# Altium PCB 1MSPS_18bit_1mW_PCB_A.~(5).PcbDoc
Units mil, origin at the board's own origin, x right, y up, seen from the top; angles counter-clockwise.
Board outline 3200 x 1700 mil, 4 copper layers (Top, Inner Layer 2, Inner Layer 3, Bottom), stack 35.4 mil thick; 66 components, 41 nets, 208 pads, 43 vias.
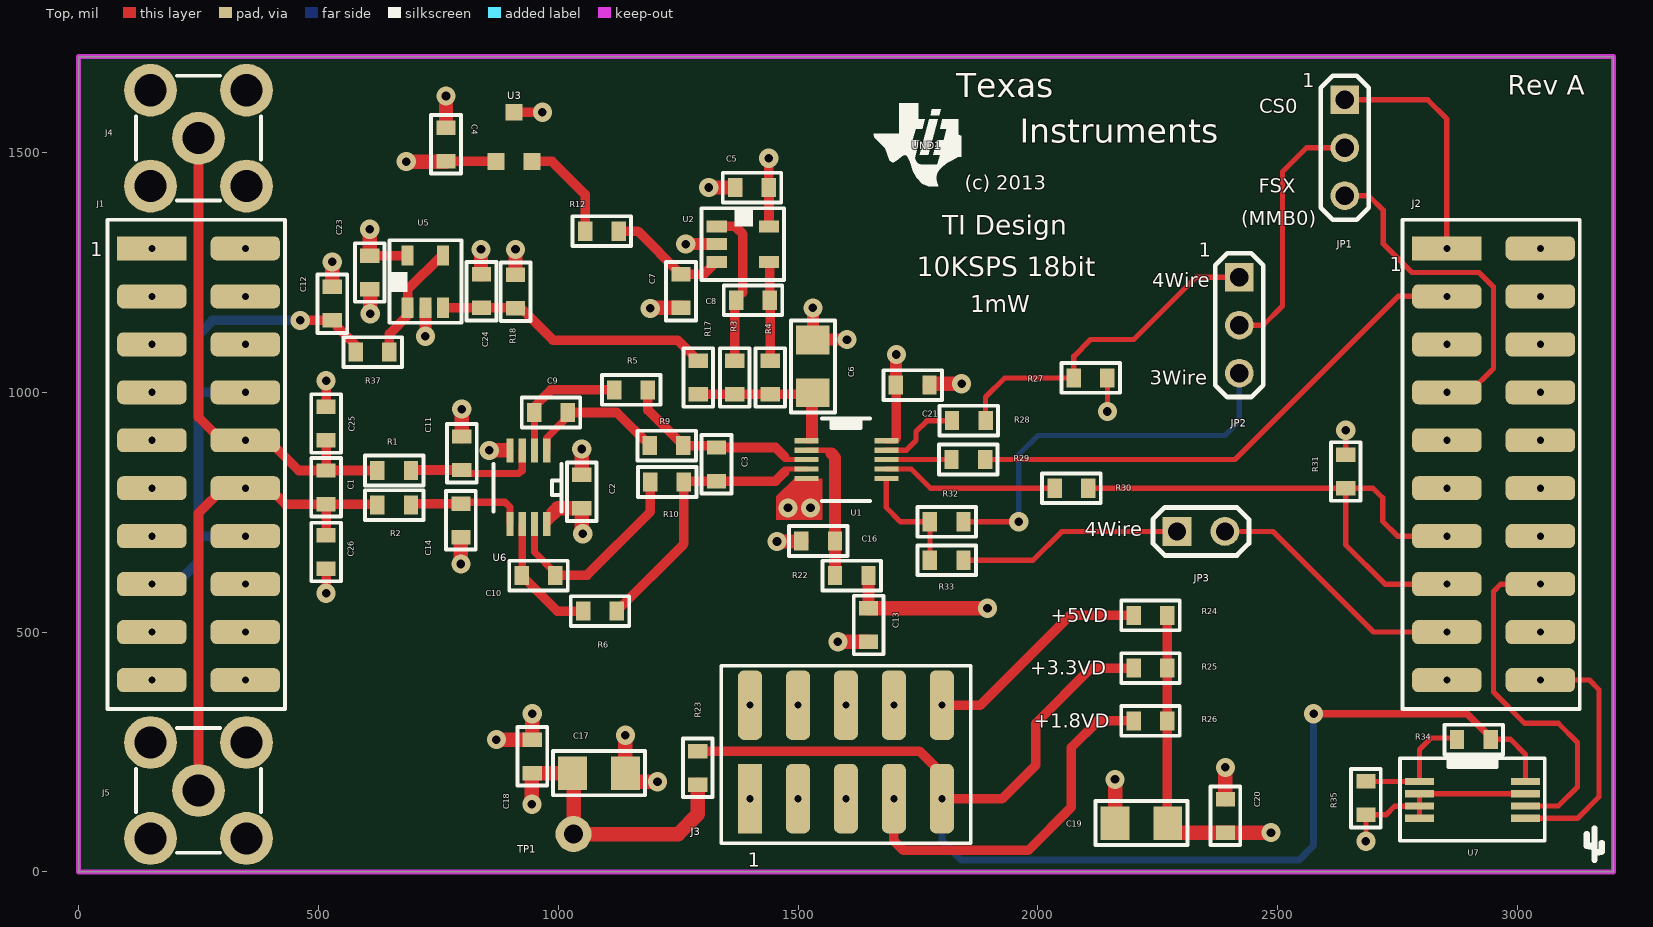
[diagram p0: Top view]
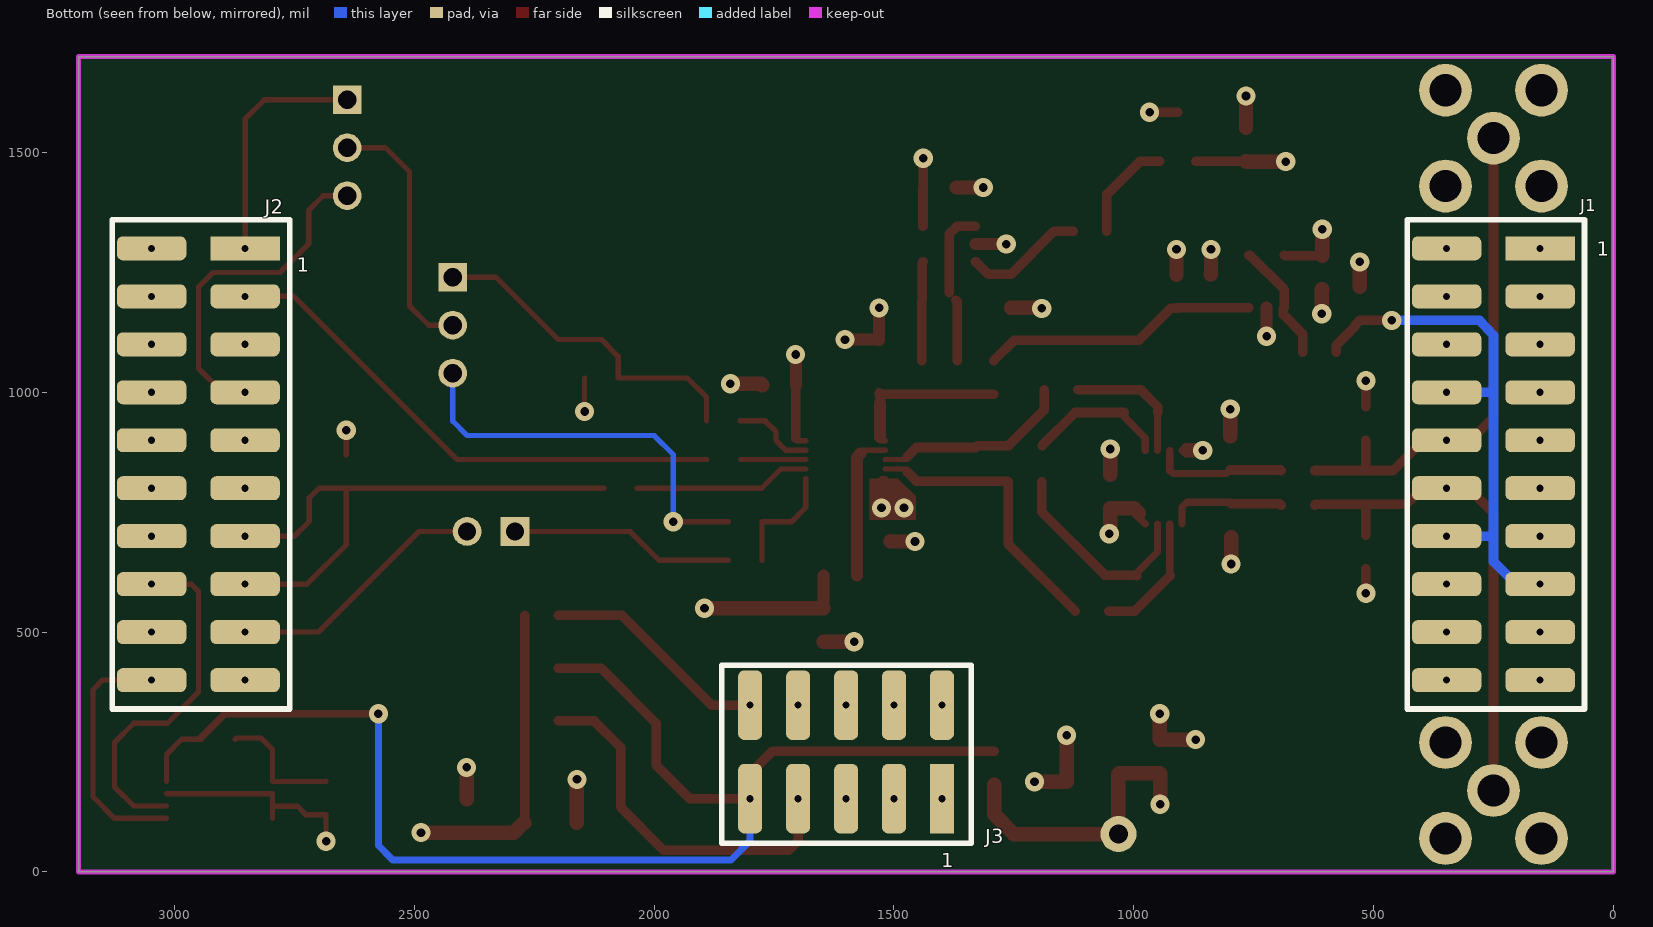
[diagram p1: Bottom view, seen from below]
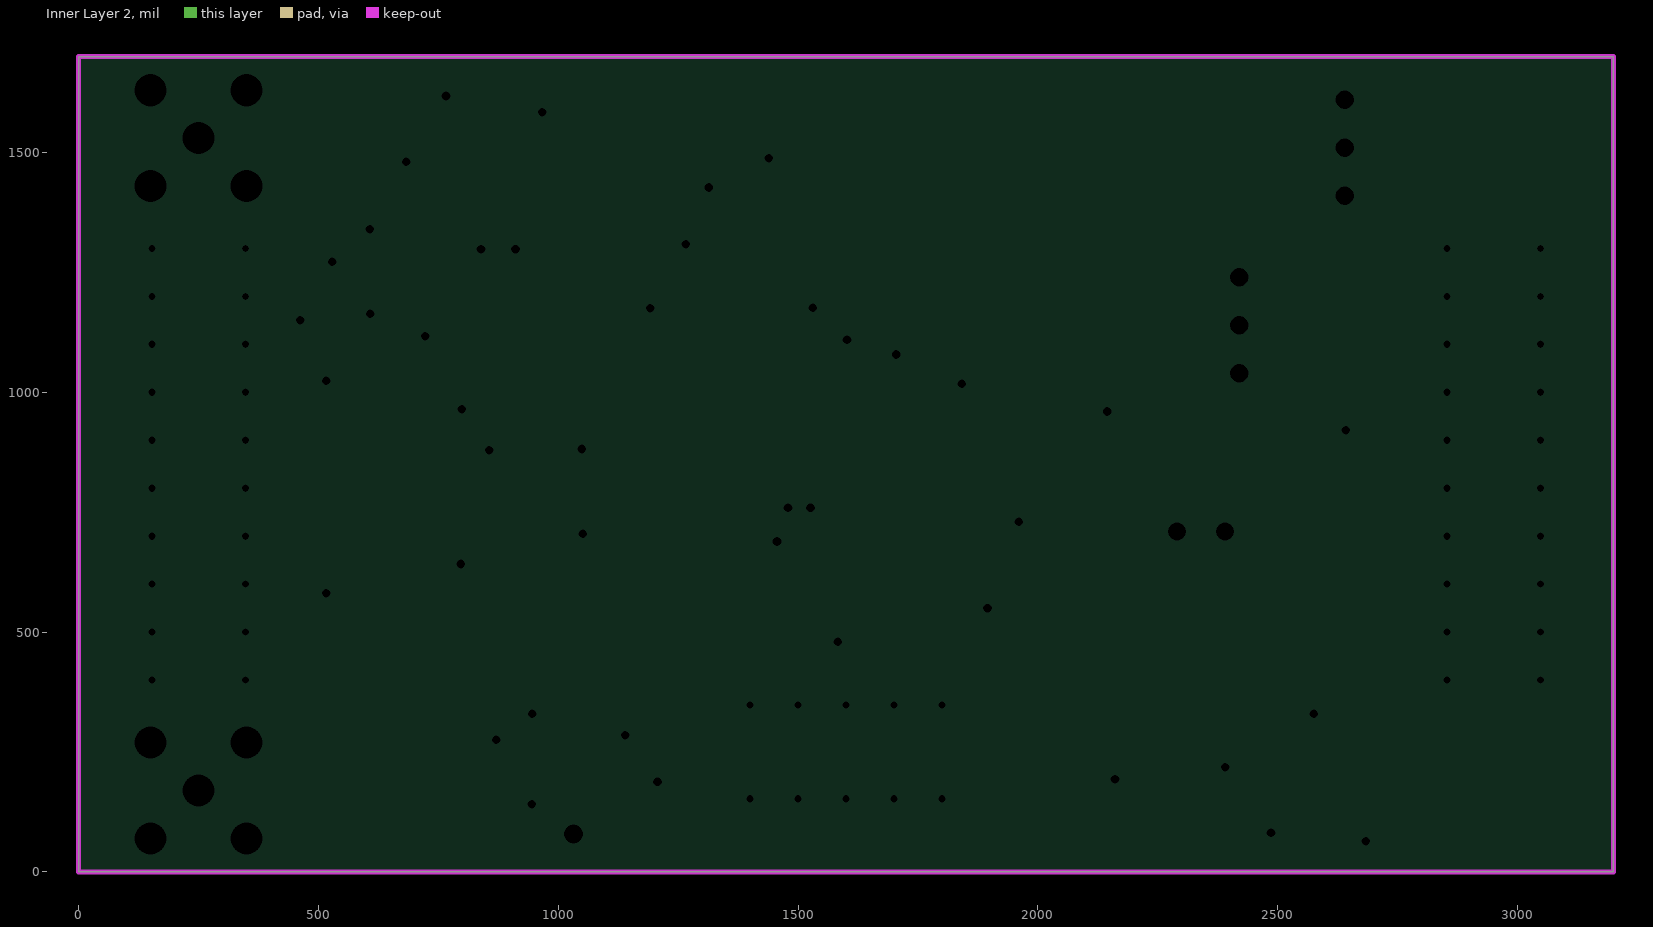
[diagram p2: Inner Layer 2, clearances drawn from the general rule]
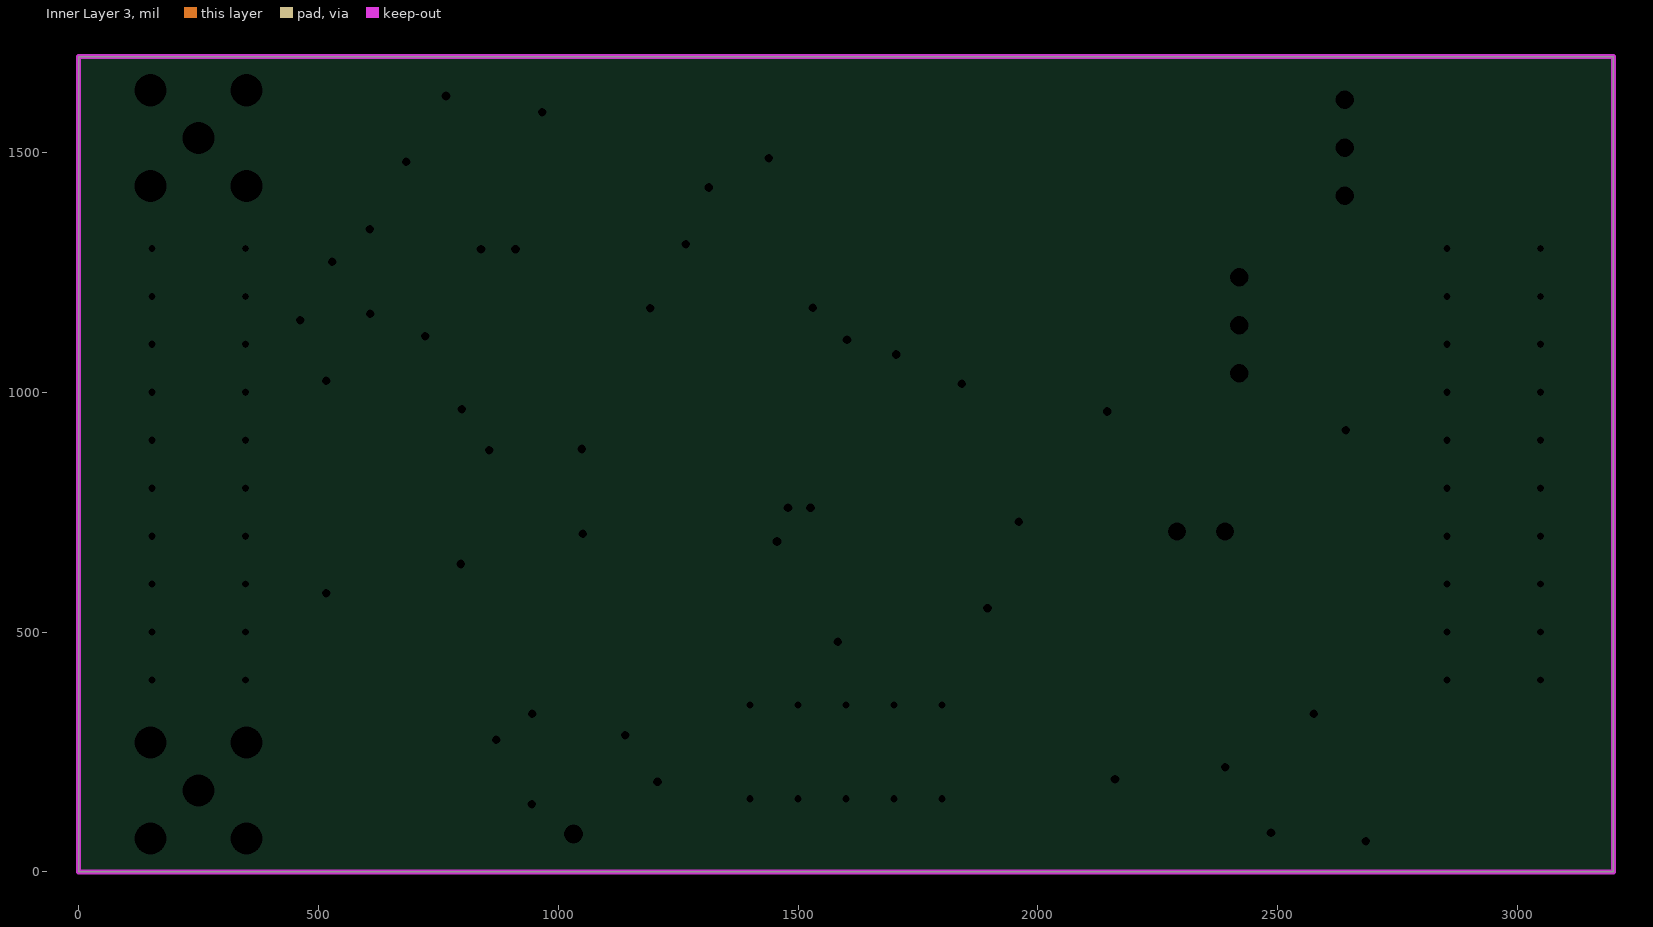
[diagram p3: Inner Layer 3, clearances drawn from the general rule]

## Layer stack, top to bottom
Top: signal copper 1.35
Dielectric: dielectric 10, FR-4, Dk 4.3
Inner Layer 2: plane copper 1.35
Dielectric: dielectric 10, FR-4, Dk 4.3
Inner Layer 3: plane copper 1.35
Dielectric: dielectric 10, FR-4, Dk 4.3
Bottom: signal copper 1.35

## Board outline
0,0 3200,0 3200,1700 0,1700

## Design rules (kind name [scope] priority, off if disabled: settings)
Clearance "'Default' PADS rule_18" [All] p1: gap=7
Clearance "'Default' PADS rule_15" [IsVia vs IsVia] p2: gap=7
ComponentClearance "'Default' PADS rule_12" [All] p1: gap=7 collisioncheckmode=3 verticalgap=10 showdistances=FALSE
FlightTimeFalling "'Default' PADS rule_10" [All] p1: maximum=10.00
FlightTimeRising "'Default' PADS rule_9" [All] p1: maximum=10.00
Length "'Default' PADS rule_5" [All] p1: maxlimit=50000 minlimit=0
MatchedLengths "'Default' PADS rule_11" [InNetClass('All Nets')] p1: tolerance=200 checknetsindiffpair=TRUE checkdiffpairvsdiffpair=TRUE checkothers=TRUE
MaxMinImpedance "'Default' PADS rule_8" [All] p1: minimum=50.00 maximum=150.0
ParallelSegment "'Default' PADS rule_7" [All] p1: limit=1000 gap=200
ParallelSegment "'Default' PADS rule_6" [All] p2: limit=1000 gap=200
PlaneClearance "'Default' PADS rule_14" [All] p1: clearance=7
PlaneConnect "Power Plane Connect Style for STDPCADVIA" [IsVia And (ViaDiameter=40) And (HoleSize=18)] p1: planeconnectstyle=Relief reliefexpansion=11 reliefentries=4 reliefconductorwidth=10 reliefairgap=10
PlaneConnect "Power Plane Connect Style for J3-5" [(Name='J3-5')] p2: planeconnectstyle=Relief reliefexpansion=7.5 reliefentries=4 reliefconductorwidth=20 reliefairgap=5
PlaneConnect "Power Plane Connect Style - pads with no thermal" [(Name='J2-2') Or (Name='J2-5') Or (Name='J2-6') Or (Name='J2-8') Or (Name='J2-9') Or (Name='J2-11') Or (Name='J2-12') Or (Name='J2-14') Or (Name='J2-19') Or (Name='J3-1') Or (Name='J3-2') Or (Name='J3-3') Or (Name='J3-4') Or (Name='J3-8') Or (Name='TP1-1')] p3: planeconnectstyle=NoConnect reliefexpansion=20 reliefentries=4 reliefconductorwidth=10 reliefairgap=10 // PAD - No Thermal Connect Rule
PlaneConnect "Power Plane Connect Style for J1-1" [(Name='J1-1')] p4: planeconnectstyle=Relief reliefexpansion=17.5 reliefentries=4 reliefconductorwidth=10 reliefairgap=10
PlaneConnect "Power Plane Connect Style - Via from round thru-hole global defaults" [IsVia] p5: planeconnectstyle=Relief reliefexpansion=20 reliefentries=4 reliefconductorwidth=10 reliefairgap=10
PlaneConnect "Power Plane Connect Style - Round thru-hole pad from global defaults" [IsPad And OnMultiLayer And (PadShape_MidLayer1 = 'Round') And (PadXSize_MidLayer1 = PadYSize_MidLayer1)] p6: planeconnectstyle=Relief reliefexpansion=20 reliefentries=4 reliefconductorwidth=10 reliefairgap=10
PlaneConnect "Power Plane Connect Style - Square thru-hole pad from global defaults" [IsPad And OnMultiLayer And ((PadShape_MidLayer1 = 'Rectangular') Or (PadShape_MidLayer1 = 'Octagonal') Or (PadShape_MidLayer1 = 'Rounded Rectangle')) And (PadXSize_MidLayer1 = PadYSize_MidLayer1)] p7: planeconnectstyle=Direct reliefexpansion=20 reliefentries=4 reliefconductorwidth=10 reliefairgap=10
PlaneConnect "Power Plane Connect Style - Rect thru-hole pad from global defaults" [IsPad And OnMultiLayer And ((PadShape_MidLayer1 = 'Rectangular') Or (PadShape_MidLayer1 = 'Octagonal') Or (PadShape_MidLayer1 = 'Rounded Rectangle')) And (PadXSize_MidLayer1 <> PadYSize_MidLayer1)] p8: planeconnectstyle=Direct reliefexpansion=20 reliefentries=4 reliefconductorwidth=10 reliefairgap=10
PlaneConnect "Power Plane Connect Style - Square-rect thru-hole pad from global defaults" [IsPad And OnMultiLayer And (PadShape_MidLayer1 = 'Rounded Rectangle') And (PadXSize_MidLayer1 = PadYSize_MidLayer1) And (Pad_CornerRadius_MidLayer1 = '0%')] p9: planeconnectstyle=Direct reliefexpansion=20 reliefentries=4 reliefconductorwidth=10 reliefairgap=10
PlaneConnect "Power Plane Connect Style - Oval thru-hole pad from global defaults" [IsPad And OnMultiLayer And (PadShape_MidLayer1 = 'Round') And (PadXSize_MidLayer1 <> PadYSize_MidLayer1)] p10: planeconnectstyle=Direct reliefexpansion=20 reliefentries=4 reliefconductorwidth=10 reliefairgap=10
PlaneConnect "Power Plane Connect Style - Round-oval thru-hole pad from global defaults" [IsPad And OnMultiLayer And (PadShape_MidLayer1 = 'Rounded Rectangle') And (PadXSize_MidLayer1 = PadYSize_MidLayer1) And (Pad_CornerRadius_MidLayer1 = '100%')] p11: planeconnectstyle=Direct reliefexpansion=20 reliefentries=4 reliefconductorwidth=10 reliefairgap=10
PolygonConnect "Polygon Connect Style - Bottom Round SMD from global defaults" [IsSMTPin And (PadShape_BottomLayer = 'Round') And (PadXSize_BottomLayer = PADYSize_BottomLayer) vs Layer = 'Bottom'] p1: connectstyle=Direct reliefconductorwidth=10 reliefentries=4 polygonreliefangle="45 Angle" airgapwidth=10
PolygonConnect "Polygon Connect Style - Top Round SMD from global defaults" [IsSMTPin And (PadShape_TopLayer = 'Round') And (PadXSize_TopLayer = PADYSize_TopLayer) vs Layer = 'Top'] p2: connectstyle=Direct reliefconductorwidth=10 reliefentries=4 polygonreliefangle="45 Angle" airgapwidth=10
PolygonConnect "Polygon Connect Style - Bottom Square SMD from global defaults 1" [IsSMTPin And (PadShape_BottomLayer = 'Rectangular') And (PadXSize_BottomLayer = PADYSize_BottomLayer) vs Layer = 'Bottom'] p3: connectstyle=Direct reliefconductorwidth=10 reliefentries=4 polygonreliefangle="45 Angle" airgapwidth=10
PolygonConnect "Polygon Connect Style - Bottom Square SMD from global defaults 2" [IsSMTPin And (PadShape_BottomLayer = 'Octagonal') And (PadXSize_BottomLayer = PADYSize_BottomLayer) vs Layer = 'Bottom'] p4: connectstyle=Direct reliefconductorwidth=10 reliefentries=4 polygonreliefangle="45 Angle" airgapwidth=10
PolygonConnect "Polygon Connect Style - Bottom Square SMD from global defaults 3" [IsSMTPin And (PadShape_BottomLayer = 'Rounded Rectangle') And (PadXSize_BottomLayer = PADYSize_BottomLayer) vs Layer = 'Bottom'] p5: connectstyle=Direct reliefconductorwidth=10 reliefentries=4 polygonreliefangle="45 Angle" airgapwidth=10
PolygonConnect "Polygon Connect Style - Top Square SMD from global defaults 1" [IsSMTPin And (PadShape_TopLayer = 'Rectangular') And (PadXSize_TopLayer = PADYSize_TopLayer) vs Layer = 'Top'] p6: connectstyle=Direct reliefconductorwidth=10 reliefentries=4 polygonreliefangle="45 Angle" airgapwidth=10
PolygonConnect "Polygon Connect Style - Top Square SMD from global defaults 2" [IsSMTPin And (PadShape_TopLayer = 'Octagonal') And (PadXSize_TopLayer = PADYSize_TopLayer) vs Layer = 'Top'] p7: connectstyle=Direct reliefconductorwidth=10 reliefentries=4 polygonreliefangle="45 Angle" airgapwidth=10
PolygonConnect "Polygon Connect Style - Top Square SMD from global defaults 3" [IsSMTPin And (PadShape_TopLayer = 'Rounded Rectangle') And (PadXSize_TopLayer = PADYSize_TopLayer) vs Layer = 'Top'] p8: connectstyle=Direct reliefconductorwidth=10 reliefentries=4 polygonreliefangle="45 Angle" airgapwidth=10
PolygonConnect "Polygon Connect Style - Bottom Rect SMD from global defaults 1" [IsSMTPin And (PadShape_BottomLayer = 'Rectangular') And (PadXSize_BottomLayer <> PADYSize_BottomLayer) vs Layer = 'Bottom'] p9: connectstyle=Direct reliefconductorwidth=10 reliefentries=4 polygonreliefangle="45 Angle" airgapwidth=10
PolygonConnect "Polygon Connect Style - Bottom Rect SMD from global defaults 2" [IsSMTPin And (PadShape_BottomLayer = 'Octagonal') And (PadXSize_BottomLayer <> PADYSize_BottomLayer) vs Layer = 'Bottom'] p10: connectstyle=Direct reliefconductorwidth=10 reliefentries=4 polygonreliefangle="45 Angle" airgapwidth=10
PolygonConnect "Polygon Connect Style - Bottom Rect SMD from global defaults 3" [IsSMTPin And (PadShape_BottomLayer = 'Rounded Rectangle') And (PadXSize_BottomLayer <> PADYSize_BottomLayer) vs Layer = 'Bottom'] p11: connectstyle=Direct reliefconductorwidth=10 reliefentries=4 polygonreliefangle="45 Angle" airgapwidth=10
PolygonConnect "Polygon Connect Style - Bottom Square-rect SMD pad from global defaults" [IsSMTPin And (PadShape_BottomLayer = 'Rounded Rectangle') And (PadXSize_BottomLayer = PADYSize_BottomLayer) And (Pad_CornerRadius_BottomLayer = '0%') vs Layer = 'Bottom'] p12: connectstyle=Direct reliefconductorwidth=10 reliefentries=4 polygonreliefangle="45 Angle" airgapwidth=10
PolygonConnect "Polygon Connect Style - Top Rect SMD from global defaults 1" [IsSMTPin And (PadShape_TopLayer = 'Rectangular') And (PadXSize_TopLayer <> PADYSize_TopLayer) vs Layer = 'Top'] p13: connectstyle=Direct reliefconductorwidth=10 reliefentries=4 polygonreliefangle="45 Angle" airgapwidth=10
PolygonConnect "Polygon Connect Style - Top Rect SMD from global defaults 2" [IsSMTPin And (PadShape_TopLayer = 'Octagonal') And (PadXSize_TopLayer <> PADYSize_TopLayer) vs Layer = 'Top'] p14: connectstyle=Direct reliefconductorwidth=10 reliefentries=4 polygonreliefangle="45 Angle" airgapwidth=10
PolygonConnect "Polygon Connect Style - Top Rect SMD from global defaults 3" [IsSMTPin And (PadShape_TopLayer = 'Rounded Rectangle') And (PadXSize_TopLayer <> PADYSize_TopLayer) vs Layer = 'Top'] p15: connectstyle=Direct reliefconductorwidth=10 reliefentries=4 polygonreliefangle="45 Angle" airgapwidth=10
PolygonConnect "Polygon Connect Style - Top Square-rect SMD pad from global defaults" [IsSMTPin And (PadShape_TopLayer = 'Rounded Rectangle') And (PadXSize_TopLayer = PADYSize_TopLayer) And (Pad_CornerRadius_TopLayer = '0%') vs Layer = 'Top'] p16: connectstyle=Direct reliefconductorwidth=10 reliefentries=4 polygonreliefangle="45 Angle" airgapwidth=10
PolygonConnect "Polygon Connect Style - Bottom Oval SMD from global defaults" [IsSMTPin And (PadShape_BottomLayer = 'Round') And (PadXSize_BottomLayer <> PADYSize_BottomLayer) vs Layer = 'Bottom'] p17: connectstyle=Direct reliefconductorwidth=10 reliefentries=4 polygonreliefangle="45 Angle" airgapwidth=10
PolygonConnect "Polygon Connect Style - Bottom Round-oval SMD pad from global defaults" [IsSMTPin And (PadShape_BottomLayer = 'Rounded Rectangle') And (PadXSize_BottomLayer = PADYSize_BottomLayer) And (Pad_CornerRadius_BottomLayer = '100%') vs Layer = 'Bottom'] p18: connectstyle=Direct reliefconductorwidth=10 reliefentries=4 polygonreliefangle="45 Angle" airgapwidth=10
PolygonConnect "Polygon Connect Style - Top Oval SMD from global defaults" [IsSMTPin And (PadShape_TopLayer = 'Round') And (PadXSize_TopLayer <> PADYSize_TopLayer) vs Layer = 'Top'] p19: connectstyle=Direct reliefconductorwidth=10 reliefentries=4 polygonreliefangle="45 Angle" airgapwidth=10
PolygonConnect "Polygon Connect Style - Top Round-oval SMD pad from global defaults" [IsSMTPin And (PadShape_TopLayer = 'Rounded Rectangle') And (PadXSize_TopLayer = PADYSize_TopLayer) And (Pad_CornerRadius_TopLayer = '100%') vs Layer = 'Top'] p20: connectstyle=Direct reliefconductorwidth=10 reliefentries=4 polygonreliefangle="45 Angle" airgapwidth=10
PolygonConnect "Polygon Connect Style - Via from round thru-hole global defaults_19" [IsVia] p21: connectstyle=Relief reliefconductorwidth=10 reliefentries=4 polygonreliefangle="90 Angle" airgapwidth=10
PolygonConnect "Polygon Connect Style - Bottom Round thru-hole pad from global defaults" [IsPad And OnMultiLayer And (PadShape_BottomLayer = 'Round') And (PadXSize_BottomLayer = PADYSize_BottomLayer) vs Layer = 'Bottom'] p22: connectstyle=Relief reliefconductorwidth=10 reliefentries=4 polygonreliefangle="90 Angle" airgapwidth=10
PolygonConnect "Polygon Connect Style - Via from round thru-hole global defaults" [IsVia] p23: connectstyle=Relief reliefconductorwidth=10 reliefentries=4 polygonreliefangle="90 Angle" airgapwidth=10
PolygonConnect "Polygon Connect Style - Top Round thru-hole pad from global defaults" [IsPad And OnMultiLayer And (PadShape_TopLayer = 'Round') And (PadXSize_TopLayer = PADYSize_TopLayer) vs Layer = 'Top'] p24: connectstyle=Relief reliefconductorwidth=10 reliefentries=4 polygonreliefangle="90 Angle" airgapwidth=10
PolygonConnect "Polygon Connect Style - Bottom Square thru-hole pad from global defaults" [IsPad And OnMultiLayer And ((PadShape_BottomLayer = 'Rectangular') Or (PadShape_BottomLayer = 'Octagonal') Or (PadShape_BottomLayer = 'Rounded Rectangle')) And (PadXSize_BottomLayer = PADYSize_BottomLayer) vs Layer = 'Bottom'] p25: connectstyle=Direct reliefconductorwidth=10 reliefentries=4 polygonreliefangle="45 Angle" airgapwidth=10
PolygonConnect "Polygon Connect Style - Top Square thru-hole pad from global defaults" [IsPad And OnMultiLayer And ((PadShape_TopLayer = 'Rectangular') Or (PadShape_TopLayer = 'Octagonal') Or (PadShape_TopLayer = 'Rounded Rectangle')) And (PadXSize_TopLayer = PADYSize_TopLayer) vs Layer = 'Top'] p26: connectstyle=Direct reliefconductorwidth=10 reliefentries=4 polygonreliefangle="45 Angle" airgapwidth=10
PolygonConnect "Polygon Connect Style - Bottom Rect thru-hole pad from global defaults" [IsPad And OnMultiLayer And ((PadShape_BottomLayer = 'Rectangular') Or (PadShape_BottomLayer = 'Octagonal') Or (PadShape_BottomLayer = 'Rounded Rectangle')) And (PadXSize_BottomLayer <> PADYSize_BottomLayer) vs Layer = 'Bottom'] p27: connectstyle=Direct reliefconductorwidth=10 reliefentries=4 polygonreliefangle="45 Angle" airgapwidth=10
PolygonConnect "Polygon Connect Style - Bottom Square-rect thru-hole pad from global defaults" [IsPad And OnMultiLayer And (PadShape_BottomLayer = 'Rounded Rectangle') And (PadXSize_BottomLayer = PADYSize_BottomLayer) And (Pad_CornerRadius_BottomLayer = '0%') vs Layer = 'Bottom'] p28: connectstyle=Direct reliefconductorwidth=10 reliefentries=4 polygonreliefangle="45 Angle" airgapwidth=10
PolygonConnect "Polygon Connect Style - Top Rect thru-hole pad from global defaults" [IsPad And OnMultiLayer And ((PadShape_TopLayer = 'Rectangular') Or (PadShape_TopLayer = 'Octagonal') Or (PadShape_TopLayer = 'Rounded Rectangle')) And (PadXSize_TopLayer <> PADYSize_TopLayer) vs Layer = 'Top'] p29: connectstyle=Direct reliefconductorwidth=10 reliefentries=4 polygonreliefangle="45 Angle" airgapwidth=10
PolygonConnect "Polygon Connect Style - Top Square-rect thru-hole pad from global defaults" [IsPad And OnMultiLayer And (PadShape_TopLayer = 'Rounded Rectangle') And (PadXSize_TopLayer = PADYSize_TopLayer) And (Pad_CornerRadius_TopLayer = '0%') vs Layer = 'Top'] p30: connectstyle=Direct reliefconductorwidth=10 reliefentries=4 polygonreliefangle="45 Angle" airgapwidth=10
PolygonConnect "Polygon Connect Style - Bottom Oval thru-hole pad from global defaults" [IsPad And OnMultiLayer And (PadShape_BottomLayer = 'Round') And (PadXSize_BottomLayer <> PADYSize_BottomLayer) vs Layer = 'Bottom'] p31: connectstyle=Direct reliefconductorwidth=10 reliefentries=4 polygonreliefangle="45 Angle" airgapwidth=10
PolygonConnect "Polygon Connect Style - Bottom Round-oval thru-hole pad from global defaults" [IsPad And OnMultiLayer And (PadShape_BottomLayer = 'Rounded Rectangle') And (PadXSize_BottomLayer = PADYSize_BottomLayer) And (Pad_CornerRadius_BottomLayer = '100%') vs Layer = 'Bottom'] p32: connectstyle=Direct reliefconductorwidth=10 reliefentries=4 polygonreliefangle="45 Angle" airgapwidth=10
PolygonConnect "Polygon Connect Style - Top Oval thru-hole pad from global defaults" [IsPad And OnMultiLayer And (PadShape_TopLayer = 'Round') And (PadXSize_TopLayer <> PADYSize_TopLayer) vs Layer = 'Top'] p33: connectstyle=Direct reliefconductorwidth=10 reliefentries=4 polygonreliefangle="45 Angle" airgapwidth=10
PolygonConnect "Polygon Connect Style - Top Round-oval thru-hole pad from global defaults" [IsPad And OnMultiLayer And (PadShape_TopLayer = 'Rounded Rectangle') And (PadXSize_TopLayer = PADYSize_TopLayer) And (Pad_CornerRadius_TopLayer = '100%') vs Layer = 'Top'] p34: connectstyle=Direct reliefconductorwidth=10 reliefentries=4 polygonreliefangle="45 Angle" airgapwidth=10
PolygonConnect [All] p35: connectstyle=Relief reliefconductorwidth=10 reliefentries=4 polygonreliefangle="90 Angle" airgapwidth=10
RoutingLayers "'Default' PADS rule_3" [All] p1: top layer_v5=TRUE bottom layer_v5=TRUE
RoutingPriority "'Default' PADS rule_2" [All] p1: routingpriority=3
RoutingTopology "'Default' PADS rule" [All] p1: topology=Shortest
RoutingVias "'Default' PADS rule_4" [All] p1: holewidth=37 width=55 viastyle="Through Hole" minholewidth=37 minwidth=55 maxholewidth=37 maxwidth=55
SMDToCorner "'Default' PADS rule_16" [All] p1: distance=70000
SMDToPlane "'Default' PADS rule_17" [All] p1: distance=70000
SilkscreenOverComponentPads [All] p1: minsilkscreentomaskgap=10
SolderMaskExpansion "Solder Mask Expansion from CAM settings" [All] p1: expansion=1
Width "'Default' PADS rule_13" [All] p1: maxlimit=30 minlimit=10 preferedwidth=20
21 further rules are at their usual default settings.

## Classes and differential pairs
net class CLASS_0: AGND

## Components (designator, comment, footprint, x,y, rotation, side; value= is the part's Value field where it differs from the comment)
C1 "C603" C603 516,802 r90 top
C2 "C603" C603 1049,793 r90 top
C3 "C603" C603 1330,850 r90 top
C4 "C603" C603 766,1517 r270 top
C5 "C603" C603 1404,1427 r180 top
C6 "C1206" C1206 1531,1054 r90 top
C7 "C603" C603 1256,1211 r90 top
C8 "C603" C603 1406,1192 r0 top
C9 "C603" C603 985,958 r0 top
C10 "C603" C603 959,618 r0 top
C11 "C603" C603 799,873 r270 top
C12 "C603" C603 529,1185 r270 top
C13 "C603" C603 1647,515 r90 top
C14 "C603" C603 797,733 r90 top
C16 "C603" C603 1542,690 r0 top
C17 "C1206" C1206 1085,206 r0 top
C18 "C603" C603 946,241 r270 top
C19 "C1206" C1206 2216,102 r180 top
C20 "C603" C603 2391,117 r270 top
C21 "C603" C603 1739,1015 r180 top
C23 "C603" C603 607,1250 r270 top
C24 "C603" C603 840,1211 r270 top
C25 "C603" C603 516,935 r270 top
C26 "C603" C603 516,667 r90 top
J1 "HEADER_TSM-110-XX-DV_TH" HEADER_TSM-110-XX-DV_TH 250,850 r270 top
J2 "HEADER_TSM-110-XX-DV_TH" HEADER_TSM-110-XX-DV_TH 2950,850 r270 top
J3 "HEADER_TSM-105-XX-DV_THA" HEADER_TSM-105-XX-DV_THA 1600,250 r0 top
J4 "CONNECTOR_SMA" CONNECTOR_SMA 250,1530 r0 top
J5 "CONNECTOR_SMA" CONNECTOR_SMA 250,170 r0 top
JP1 "HDR100_1X3" HDR100_1X3 2640,1610 r270 top
JP2 "HDR100_1X3" HDR100_1X3 2420,1240 r270 top
JP3 "HDR100_1X2" HDR100_1X2 2290,710 r0 top
R1 "R0603" R0603 658,837 r180 top
R2 "R0603" R0603 658,765 r180 top
R3 "R0603" R0603 1368,1031 r270 top
R4 "R0603" R0603 1442,1031 r270 top
R5 "R0603" R0603 1152,1005 r0 top
R6 "R0603" R0603 1087,544 r0 top
R9 "R0603" R0603 1226,889 r0 top
R10 "R0603" R0603 1227,813 r0 top
R12 "R0603" R0603 1091,1336 r0 top
R17 "R0603" R0603 1292,1031 r270 top
R18 "R0603" R0603 911,1210 r90 top
R22 "R0603" R0603 1612,618 r180 top
R23 "R0603" R0603 1291,217 r90 top
R24 "R0603" R0603 2235,535 r0 top
R25 "R0603" R0603 2235,425 r0 top
R26 "R0603" R0603 2235,315 r0 top
R27 "R0603" R0603 2110,1030 r180 top
R28 "R0603" R0603 1856,941 r0 top
R29 "R0603" R0603 1855,860 r0 top
R30 "R0603" R0603 2070,800 r0 top
R31 "R0603" R0603 2642,835 r270 top
R32 "R0603" R0603 1810,730 r0 top
R33 "R0603" R0603 1810,650 r0 top
R34 "R0603" R0603 2909,276 r0 top
R35 "R0603" R0603 2684,154 r270 top
R37 "R0603" R0603 613,1084 r180 top
TP1 "TH-40" TH-40 1032,79 r0 top
U1 "DGS_10P" DGS_10P 1600,860.25 r0 top
U2 "DBV-5" DBV-5 1385,1309 r0 top
U3 "SOT-23" SOT-23 908,1534 r0 top
U5 "DBV-5" DBV-5 723,1231 r90 top
U6 "DGK8" DGK8 936,801 r270 top
U7 "TSSOP8" TSSOP8 2906,151 r0 top
UND1 "TIBUG2-NEW" TIBUG2-NEW 1761,1514 r0 top

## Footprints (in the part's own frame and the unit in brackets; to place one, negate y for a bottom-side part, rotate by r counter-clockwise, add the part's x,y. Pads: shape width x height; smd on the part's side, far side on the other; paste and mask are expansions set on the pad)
C603 [mil]
  rect 30x40 smd mask+2: 1(-35,0) 2(35,0)
  silkscreen extent -61,-31 61,31
C1206 [mil]
  rect 60x70 smd mask+2: 1(-55,0) 2(55,0)
  silkscreen extent -96,-46 96,46
CONNECTOR_SMA [mil]
  round 110 hole 67 mask+2.5: 1(0,0) 2(100,100) 3(100,-100) 4(-100,-100) 5(-100,100)
  silkscreen extent -130,-130 130,130
DBV-5 [mil]
  rect 42x25 smd mask+1.5: 1(-54.5,37) 2(-54.5,0) 3(-54.5,-37) 4(54.5,-37) 5(54.5,37)
  silkscreen extent -86,-75 86,75
DGK8 [mil]
  rect 50x15 smd mask+1.5: 1(-78,40) 2(-78,14.4) 3(-78,-11.2) 4(-78,-36.8) 5(75.6,-36.8) 6(75.6,-11.2) 7(75.6,14.4) 8(75.6,40)
  silkscreen extent -50,-71 50,71
DGS_10P [mil]
  rect 50x11 smd mask+1.5: 1(-82,39) 2(-82,19.3) 3(-82,-0.4) 4(-82,-20.1) 5(-82,-39.8) 6(84,-39.8) 7(84,-20.1) 8(84,-0.4) 9(84,19.3) 10(84,39)
  silkscreen extent -50,-87 50,85
HDR100_1X2 [mil]
  rect 60x60 hole 38 mask+2.5: 1(0,0)
  round 60 hole 38 mask+2.5: 2(100,0)
  silkscreen extent -50,-50 150,50
HDR100_1X3 [mil]
  rect 60x60 hole 38 mask+2.5: 1(0,0)
  round 60 hole 38 mask+2.5: 2(100,0) 3(200,0)
  silkscreen extent -50,-50 250,50
HEADER_TSM-105-XX-DV_THA [mil]
  rect 50x145 hole 15 mask+2.5: 1(-200.1,-97.2)
  rrect50% 50x145 hole 15 mask+2.5: 2(-200.1,97.8) 3(-100.1,-97.2) 4(-100.1,97.8) 5(-0.1,-97.2) 6(-0.1,97.8) 7(99.9,-97.2) 8(99.9,97.8) 9(199.9,-97.2) 10(199.9,97.8)
  silkscreen extent -260,-190 260,180
HEADER_TSM-110-XX-DV_TH [mil]
  rect 50x145 hole 15 mask+2.5: 1(-450.1,-97.2)
  rrect50% 50x145 hole 15 mask+2.5: 2(-450.1,97.8) 3(-350.1,-97.2) 4(-350.1,97.8) 5(-250.1,-97.2) 6(-250.1,97.8) 7(-150.1,-97.2) 8(-150.1,97.8) 9(-50.1,-97.2) 10(-50.1,97.8) 11(49.9,-97.2) 12(49.9,97.8) 13(149.9,-97.2) 14(149.9,97.8) 15(249.9,-97.2) 16(249.9,97.8) 17(349.9,-97.2) 18(349.9,97.8) 19(449.9,-97.2) 20(449.9,97.8)
  silkscreen extent -510,-190 510,180
R0603 [mil]
  rect 30x40 smd mask+2: 1(-35,0) 2(35,0)
  silkscreen extent -61,-31 61,31
SOT-23 [mil]
  rect 35x35 smd: 1(-37.5,-52.5) 2(37.5,-52.5) 3(0,50)
TH-40 [mil]
  round 75 hole 40 mask+2.5: 1(0,0)
TIBUG2-NEW [mil]
  silkscreen extent -103,-84 79,89
TSSOP8 [mil]
  rect 60x15 smd mask+1.5: 1(-110.1,37.6) 2(-110.1,12) 3(-110.1,-13.6) 4(-110.1,-39.2) 5(110.9,-39.2) 6(110.9,-13.6) 7(110.9,12) 8(110.9,37.6)
  silkscreen extent -151,-86 151,86

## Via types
v1: diameter 40/40 (per signal layer), hole 18, Top to Bottom, 43 vias

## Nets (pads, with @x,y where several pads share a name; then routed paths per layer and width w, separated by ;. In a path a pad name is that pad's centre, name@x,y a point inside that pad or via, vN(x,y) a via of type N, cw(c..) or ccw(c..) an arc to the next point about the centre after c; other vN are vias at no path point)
$$$2464: C7.2 R12.2 U2.3 | length 252.5
  Top w20: R12.2 1166,1336 C7.2 1303,1246 1329,1272 U2.3
$$$7948: C16.2 R22.2 U1.2 | length 314.8
  Top w11: U1.2 1568,879.55 1570,877.55 1570,873 ; C16.2 C16.2@1577,696
  Top w25: 1570,873 1577,864 C16.2@1577,696 ; R22.2 C16.2
$$$13081: R12.1 U3.2 | length 215.6
  Top w20: U3.2 987,1481.5 1056,1412.5 R12.1
$$$14370: C8.1 R3.1 U2.1 | length 310.4
  Top w20: U2.1 1369,1346 1385,1330 C8.1@1385,1208 ; R3.1 1368,1189 C8.1
$$$14376: R37.1 U5.1 U5.4 | length 251
  Top w20: R37.1 648,1122 688,1162 688,1174.5 U5.1 686,1214 757.5,1285.5 U5.4
$$$15592: C10.1 R6.1 U6.6 | length 266.4
  Top w15: C10.1 924.8,618.8 U6.6
  Top w20: C10.1 998,544 R6.1
$$$15636: C8.2 R4.1 U2.4 | length 207
  Top w20: U2.4 1441,1270.5 C8.2 1442,1191 R4.1
$$$15662: C6.1 R3.2 R4.2 R17.2 U1.1 | length 350.6
  Top w11: U1.1 1529,899.25 1529,907
  Top w20: R17.2 R3.2 R4.2 C6.1@1531,996 ; C6.1@1529,977 1529,992 1531,994 C6.1@1531,996 ; C6.1 C6.1@1531,996
  Top w25: 1529,907 C6.1@1529,977
$$$16005: C9.1 R5.1 U6.2 | length 272.7
  Top w15: C9.1 950.4,957.6 U6.2
  Top w20: C9.1 950,970 985,1005 R5.1
$$$16016: C9.2 R9.1 U6.1 | length 296.8
  Top w15: U6.1 976,905 1019,948 1019,957 C9.2
  Top w20: C9.2 1122,958 R9.1
$$$16459: C10.2 R10.1 U6.7 | length 440
  Top w15: U6.7 950.4,667 995,622.4 C10.2@995,619
  Top w20: C10.2 995,619 1060,619 1192,751 R10.1
$$$17367: J2.17 JP3.2 | length 549.7
  Top w11: JP3.2 2490.1,710 2700,500.1 J2.17
$$$17384: J2.3 R29.2 | length 1103.7
  Top w11: R29.2 2411,860 2751.1,1200.1 J2.3
$$$17558: J2.7 JP1.3 | length 717.5
  Top w11: JP1.3 2690,1410 2720,1380 2720,1310 2780,1250 2920,1250 2950,1220 2950,1050.1 2900,1000.1 J2.7
$$$17563: J2.1 JP1.1 | length 499.3
  Top w11: JP1.1 2812.8,1610 2852.8,1570 J2.1
$$$19122: C3.2 R5.2 R9.2 U1.3 | length 419.3
  Top w11: 1472,866 1472,859.85 U1.3
  Top w20: R5.2 1187,963 R9.2 1326,889 C3.2 1453,885 1472,866
$$$19127: C3.1 R6.2 R10.2 U1.4 | length 597.8
  Top w11: 1472,834 1472,840 1518,840 U1.4
  Top w20: R6.2 1262,684 R10.2 1264,815 C3.1 1453,815 1472,834
$$$21346: C24.2 R17.1 R18.1 U5.3 | length 578.4
  Top w20: U5.3 760.5,1176 C24.2 911,1176 R18.1 923,1175 989,1109 1249,1109 R17.1
$$$22242: J2.16 U7.6 | length 749.8
  Top w11: U7.6 3085,137.4 3125,177.4 3125,270 3085,310 3015,310 2950,375 2950,585 2965.1,600.1 J2.16
$$$22255: J2.20 U7.5 | length 525.5
  Top w11: U7.5 3125,111.8 3170,156.8 3170,380 3149.9,400.1 J2.20
$$$22414: R34.1 R35.1 U7.1 | length 267.8
  Top w11: R35.1 2684.4,188.6 U7.1 2795.9,255 2820,279.1 2870.9,279.1 R34.1
$$$23087: JP2.1 R27.2 R28.2 | length 707.9
  Top w11: R28.2 1891,990 1931,1030 R27.2 2075,1075 2110,1110 2200,1110 2330,1240 JP2.1
$$$23256: JP1.2 JP2.2 | length 537.3
  Top w11: JP2.2 2470,1140 2510,1180 2510,1460 2560,1510 JP1.2
$$$23301: R28.1 U1.9 | length 173.3
  Top w11: U1.9 1726,879.55 1746,899.55 1746,918 1768.55,940.55 1820.55,940.55 R28.1
$$$23343: R29.1 U1.8 | length 136.2
  Top w11: U1.8 1820,859.85 R29.1
$$$23357: R30.1 U1.7 | length 367.6
  Top w11: U1.7 1736,840.15 1776.15,800 R30.1
$$$23386: JP2.3 R32.2 | length 844
  Top w11: R32.2 v1(1960,730)
  Bottom w11: v1(1960,730) 1960,870 2000,910 2390,910 2420,940 JP2.3
$$$23391: R32.1 R33.1 U1.6 | length 243.9
  Top w11: U1.6 1684,760 1714,730 R32.1 R33.1
$$$23695: JP3.1 R33.2 | length 469.9
  Top w11: R33.2 1990,650 2050,710 JP3.1
$$$23868: J2.13 J2.15 R30.2 R31.2 | length 1180.5
  Top w11: R30.2 R31.2 ; J2.15 2724,600.1 2642,682.1 R31.2 ; J2.13 2750,700.1 2719,731.1 2719,780 2699,800 R31.2
$$$31818: C14.2 R2.1 U6.5 | length 248.4
  Top w15: C14.2 800,771 889.2,771 899.2,761 U6.5
  Top w20: R2.1 696,768 C14.2
$$$31881: C11.2 R1.1 U6.3 | length 280
  Top w15: C11.2 806.8,831 917.8,831 922.8,836 924.8,836 U6.3
  Top w20: R1.1 694,838 C11.2
+1.8VD: J3.7 R26.1 | length 781.2
  Top w20: J3.7 1699.9,65 1719.9,45 1980,45 2070,135 2070,260 2125,315 R26.1
+3.3VD: J3.9 R23.2 R25.1 R34.2 U7.8 | length 2848.6
  Top w11: R34.2@2944,281 R34.2 2944.9,276.9 2985,276.9 3016.9,245 U7.8
  Top w15: v1(2575,330) 2895,330 R34.2@2944,281
  Top w20: R23.2 1753,252 1799.9,205.1 J3.9 1926,152.8 1996,222.8 1996,310 2111,425 R25.1
  Bottom w15: J3.9 1799.9,65 1839.9,25 2545,25 2575,55 v1(2575,330)
+5VD: J3.10 R24.1 | length 477.6
  Top w20: J3.10 1880,347.8 2067.2,535 R24.1
A0(+): C1.2 C25.2 J1.10 J4.1 R1.2 | length 1064
  Top w20: J4.1 250,948 297.9,900.1 J1.10 396,900.1 459,837.1 515.9,837.1 C1.2 ; C25.2 C1.2 ; R1.2 C1.2
A0(-): C1.1 C26.2 J1.12 J5.1 R2.2 | length 1052.9
  Top w20: J5.1 250,748 302,800 347.7,800 J1.12 398,800.1 432.1,766 433.1,767 C1.1 ; C26.2 C1.1 ; R2.2 621,767 519,767 C1.1
AGND: C2.2 C4.1 C5.2 C6.2 C7.1 C11.1 C12.1 C13.1 C14.1 C16.1 C17.2 C18.1 C19.2 C20.1 C21.1 C23.2 C24.1 C25.1 C26.1 J1.1 J1.2 J1.3 J1.4 J1.5 J1.6 J1.7 J1.9 J1.11 J1.13 J1.16 J1.17 J1.18 J1.19 J1.20 J2.4 J2.10 J2.18 J3.5 J3.6 J4.2 J4.3 J4.4 J4.5 J5.2 J5.3 J5.4 J5.5 R18.2 R35.2 U1.5 U2.2 U3.3 U5.2 U6.4 U7.2 U7.3 U7.4 U7.7 | length 2245.9
  Top w11: v1(1479,759) 1494.07,772 U1.5@1494.07,815 ; U1.5 1526,820.45 v1(1526,759) ; v1(2684,64) R35.2 2726,119 2744,137 2795.5,137 U7.3 ; U7.4 U7.3 ; U7.7 U7.2 U7.3
  Top w15: 889,879 U6.4
  Top w20: v1(516,581) C26.1 ; C25.1 v1(516,1024) ; U3.3 v1(967,1584) ; C6.2 C6.2@1532,1110
  Top w25: v1(723,1117) U5.2 ; v1(1266,1309) U2.2 ; C6.2 v1(1531,1176) ; C6.2@1532,1110 v1(1602,1110)
  Top w30: C12.1 v1(529,1272) ; C23.2 608,1215 v1(608,1164) ; C4.1 v1(766,1618) ; v1(797,642) C14.1 ; C11.1 v1(799,965) ; v1(839,1298) 839,1246 C24.1 ; v1(856,879) 889,879 ; v1(871,276) C18.1 v1(946,330) ; R18.2 v1(911,1298) ; C2.2 v1(1049,882) ; v1(1140,285) C17.2 1140,188 v1(1207,188) ; v1(1192,1175) 1192,1176 C7.1 ; v1(1314,1427) C5.2 ; v1(1456,689) 1507,689 C16.1 ; v1(1583,480) C13.1 ; C21.1 1777,1018 v1(1841,1018) ; C19.2 v1(2161,193) ; C20.1 v1(2391,218)
AVDD: C2.1 C4.2 C5.1 C17.1 C18.2 C23.1 R23.1 TP1.1 U2.5 U3.1 U5.5 U6.8 | length 1228.6
  Top w15: U6.8 989,738.4 989,748
  Top w20: C23.1 U5.5@685,1285 ; C4.2 870,1482 U3.1 ; v1(1439,1488) C5.1 1439.5,1426.5 U2.5 ; U5.5@685,1285 U5.5 685.5,1285 U5.5@685,1285
  Top w30: C23.1 v1(607,1340) ; v1(683,1481) 766,1481 C4.2 ; v1(945,141) 945,205 C18.2 C17.1 1032,204 TP1.1 1250,79 1291,120 R23.1 ; 989,748 999,758 C2.1 1049,705 v1(1051,705)
DVDD: C13.2 C19.1 C20.2 C21.2 R22.1 R24.2 R25.2 R26.2 R27.1 R31.1 U1.10 | length 1293.5
  Top w11: U1.10 1702,899.25 1702,901 U1.10@1705,904 ; v1(2145,960) R27.1 ; R31.1 v1(2642,921)
  Top w20: C21.2 1705,1014 U1.10@1705,904 ; R24.2 R25.2 R26.2 2270,103 C19.1
  Top w25: C13.2 R22.1 ; C21.2 1704,1078 v1(1705,1079)
  Top w30: C13.2 v1(1895,550) ; C19.1 2273,102 2293,82 C20.2 v1(2486,82)
VCM: C12.2 J1.8 J1.14 J1.15 R37.2 | length 1163
  Top w20: v1(462,1150) C12.2 538,1141 538,1138 578,1098 R37.2
  Bottom w20: J1.15 203.1,600.1 250,647 250,700.1 ; J1.14 250,700.1 ; J1.8 250,1000.1 ; v1(462,1150) 279,1150 250,1119 250,1000.1 ; 250,700.1 250,1000.1
pads on no net: J2.2 J2.5 J2.6 J2.8 J2.9 J2.11 J2.12 J2.14 J2.19 J3.1 J3.2 J3.3 J3.4 J3.8

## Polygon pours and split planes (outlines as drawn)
AGND on Inner Layer 2 (split plane): 3184.9,475 3184.94,474.83 3184.88,255 3184.89,255 3184.9,15.1 15.1,15.1 15.1,1684.9 3184.9,1684.9
DVDD on Inner Layer 3 (split plane): 3173.95,26.05 1646.05,26.05 1646.05,1673.95 3173.95,1673.95
AVDD on Inner Layer 3 (split plane): 1533.95,26.05 26.05,26.05 26.05,1673.95 1533.95,1673.95

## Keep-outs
Keep-Out Layer:
  the board outline again, w10

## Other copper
Top:
  region net AGND: 1492,820 1455,783 1455,734 1550,734 1550,820 1492,820
Inner Layer 2 (plane layer: these items are gaps in the copper):
  region: 3200,0 0,0 0,1700 3200,1700 hole: 3190,1690 10,1690 10,10 3190,10 3189.98,255 3189.98,255 3190.03,475 3190,475
  lines w10: 3189.98,255 3189.98,255 ; 3189.98,255 3190,10 10,10 10,1690 3190,1690 3190,475 3190.03,475 3189.98,255
Inner Layer 3 (plane layer: these items are gaps in the copper):
  region: 3200,0 0,0 0,1700 3200,1700 hole: 3180,1680 1640,1680 1640,20 3180,20 hole: 1540,1680 20,1680 20,20 1540,20
  lines w12: 20,20 1540,20 1540,1680 20,1680 20,20 ; 1640,20 1640,1680 3180,1680 3180,20 1640,20

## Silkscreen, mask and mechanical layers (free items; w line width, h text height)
Silkscreen Top:
  region: 1570,945 1630,945 1630,925 1570,925 1570,945
  region: 2855,235 2955,235 2955,215 2855,215 2855,235
  region: 647,1250 685,1250 685,1210 647,1210 647,1250
  region: 1368,1386 1406,1386 1406,1346 1368,1346 1368,1386
  lines w12: 3144,54.16 3160,50.16 3160,25 3161,25 3161,38.03 3175,41.03 3175,61 3176,61 3176,42 3161,42 3161,91 3160,91 3160,55 3145,55 3145,79 3144,79 3144,54.16
  text "1" at 2551.43,1636 h30
  text "Rev A" at 2979.87,1621 h40
  text "Texas" at 1830.35,1615.01 h50
  text "CS0" at 2461.72,1581.5 h30
  text "Instruments" at 1962.78,1520.01 h50
  text "(c) 2013" at 1847.23,1422.15 h30
  text "FSX" at 2460.65,1416.5 h30
  text "(MMB0)" at 2424.02,1348.65 h30
  text "TI Design" at 1800.64,1328.39 h40
  text "1" at 24.43,1284 h30
  text "1" at 2335.43,1283 h30
  text "1" at 2733.43,1253 h30
  text "10KSPS 18bit" at 1747.47,1242.05 h40
  text "4Wire" at 2238.23,1218.79 h30
  text "1mW" at 1858.68,1166.5 h35
  text "3Wire" at 2233.23,1015.79 h30
  text "4Wire" at 2098.23,700.29 h30
  text "+5VD" at 2027.01,521 h30
  text "+3.3VD" at 1983.94,411 h30
  text "+1.8VD" at 1991.3,301 h30
  text "1" at 1395.43,11 h30
Silkscreen Bottom:
  lines w12: 60,340 430,340 430,1360 60,1360 60,340 ; 1339,60 1859,60 1859,431 1339,431 1339,60 ; 2760,340 3130,340 3130,1360 2760,1360 2760,340
  text "1" at 35,1285 h30
  text "1" at 2745,1251 h30
  text "1" at 1401,10 h30
Drill Drawing:
  the board outline again, w1
  text "3200mil" at 1443.18,1850.18 h50
  text "1700mil" at -516.59,812.5 h50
